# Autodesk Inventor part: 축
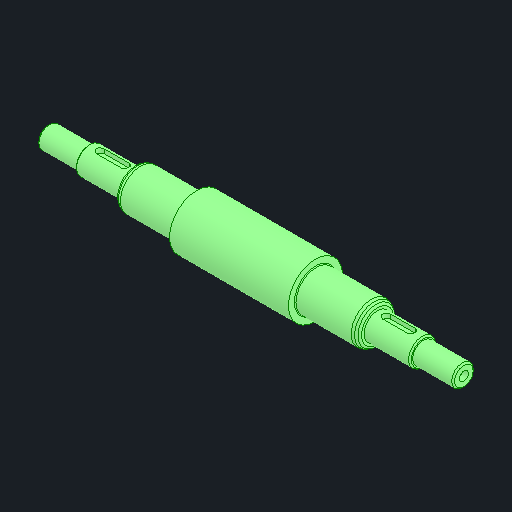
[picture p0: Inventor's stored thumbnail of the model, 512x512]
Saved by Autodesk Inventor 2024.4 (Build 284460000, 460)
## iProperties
Created: 2025-10
Part Number: 축
Material: 강철, 탄소
Document SubType Name: Modeling
Designer: user
Density: 7.85 g/cm^3
Appearance: 기본값
Author: jhkim
Sending System: Autodesk Inventor 2026
Preprocessor: ST-DEVELOPER v20.1
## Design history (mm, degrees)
feature "솔리드1"
node "솔리드2"
